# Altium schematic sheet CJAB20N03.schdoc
size 127 x 101 mm
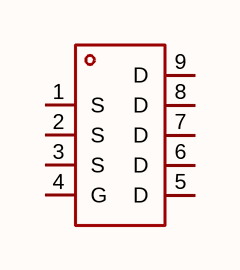
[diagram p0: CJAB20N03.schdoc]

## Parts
Q?  cjab20n03  [WDFN-8_L3.0-W3.0-P0.65-LS3.3-BL_ONSEMI_NVTFWS024N06CXXX]  (value not drawn)

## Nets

Not connected (* = marked no-connect by the designer): Q? 1(S) 2(S) 3(S) 4(G) 5(D) 6(D) 7(D) 8(D) 9(D)

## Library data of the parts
Q? = cjab20n03: 数量:1个N沟道;漏源电压(Vdss):30V;连续漏极电流(Id):20A;导通电阻(RDS(on)):8.5mΩ@10V;耗散功率(Pd):1.5W;阈值电压(Vgs(th)):3V;; Manufacturer: CJ(江苏长电/长晶); AddInBom: yes; ModelId: 79c6199f0e464bc0af2e6a4528da465e; ModelTransform: 129.921,129.921,0,0,0,0,0,0,0; Number: 1个N沟道; Drain to Source Voltage: 30V; Current - Continuous Drain(Id): 20A; Pd - Power Dissipation: 1.5W; Gate Threshold Voltage (Vgs(th)): 3V; Gate Charge(Qg): 13nC; Input Capacitance(Ciss): 823pF; Reverse Transfer Capacitance (Crss@Vds): 100pF; Type: N沟道; Output Capacitance(Coss): 138pF; Vgs: ±20V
